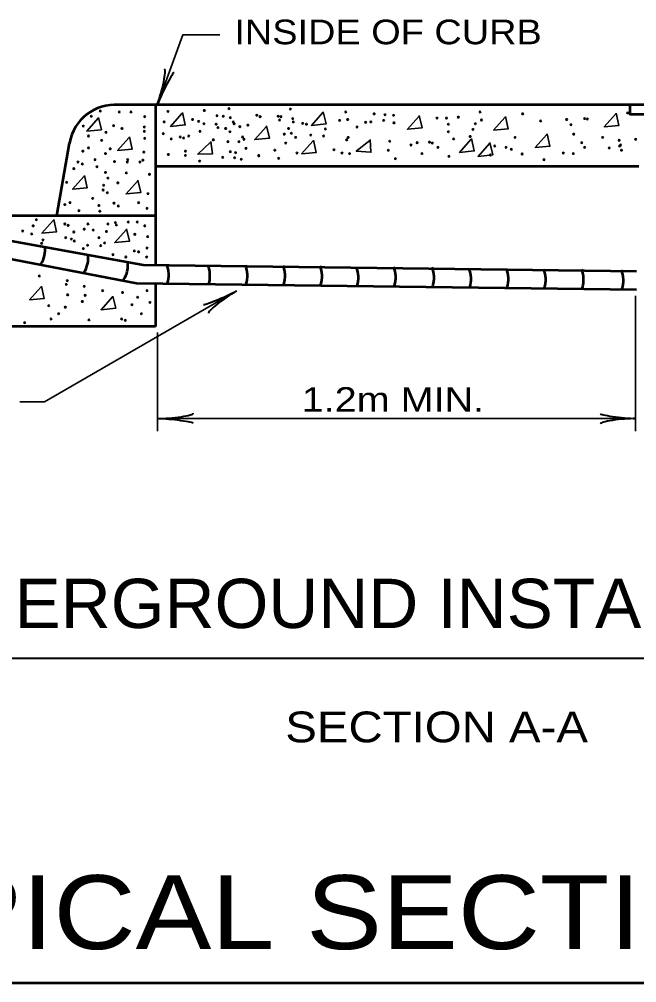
# Model space of a CAD drawing. Extents: x -90 to 623, y -379 to 75.
# Drawn here: x 22.4 to 72.5, y -115.6 to -37.4 of the extents above; entities that cross this region are included whole.
import ezdxf

# ---------------------------------------------------------------- set-up
doc = ezdxf.new("R2010")
doc.units = 0
doc.header["$LTSCALE"] = 0.8
doc.layers.add('1', color=7, linetype='Continuous', lineweight=35)

msp = doc.modelspace()

# ---------------------------------------------------------------- linework, layer by layer
at = {"layer": '1', "lineweight": 53}
for p, q in [((95.4567, -44.3181), (30.4567, -44.3181)), ((33.4567, -44.3181), (33.4567, -57.3237)), ((25.4567, -53.3181), (26.4986, -47.4093)), ((72.7067, -49.3181), (33.4567, -49.3181)), ((33.4567, -53.3181), (3.4567, -53.3181)), ((3.4567, -53.3181), (31.9376, -58.7988)), ((10.4567, -53.3181), (32.4567, -57.3053)), ((32.4567, -57.3053), (72.5202, -57.8181)), ((31.9376, -58.7988), (72.501, -59.318)), ((33.4567, -58.7824), (33.4567, -62.3181)), ((33.4567, -62.3181), (3.4567, -62.3181)), ((0.8544, -115.6087), (216.8702, -115.6087))]:
    msp.add_line(p, q, dxfattribs=at)
at = {"layer": '1'}
for p, q in [((72.4397, -59.8188), (72.4397, -70.8188)), ((33.6269, -62.8061), (33.6269, -70.8188)), ((33.6609, -69.7865), (72.4412, -69.7865))]:
    msp.add_line(p, q, dxfattribs=at)
at = {"layer": '1', "lineweight": 40}
msp.add_line((7.4085, -89.2559), (100.8059, -89.2559), dxfattribs=at)
at = {"layer": '1'}
for points in [[(33.6255, -44.2669), (35.6776, -38.6287), (38.6776, -38.6287)], [(28.8155, -45.4032), (27.8942, -46.4397), (29.0842, -46.3246), (28.8538, -45.3265)], [(35.6102, -45.0193), (34.6888, -46.0558), (35.8788, -45.9407), (35.6485, -44.9426)], [(47.0498, -44.9426), (46.1285, -45.9791), (47.3185, -45.8639), (47.0882, -44.8658)], [(54.8426, -45.2497), (53.9213, -46.2862), (55.1112, -46.171), (54.8809, -45.1729)], [(61.8292, -45.3264), (60.9079, -46.3629), (62.0979, -46.2477), (61.8676, -45.2497)], [(70.812, -45.0577), (69.8907, -46.0942), (71.0807, -45.9791), (70.8503, -44.981)], [(42.4432, -46.0942), (41.5219, -47.1307), (42.7119, -47.0156), (42.4816, -46.0175)], [(31.3107, -46.9771), (30.3893, -48.0136), (31.5793, -47.8984), (31.349, -46.9003)], [(65.2073, -46.7468), (64.286, -47.7833), (65.476, -47.6682), (65.2457, -46.6701)], [(37.9037, -47.3589), (36.8955, -48.3112), (38.091, -48.3002), (37.9485, -47.2858)], [(46.2437, -47.2458), (45.3223, -48.2823), (46.5123, -48.1672), (46.282, -47.1691)], [(50.8516, -47.1979), (49.7642, -48.0587), (50.9562, -48.1519), (50.9026, -47.129)], [(59.0652, -47.1307), (58.1439, -48.1672), (59.3339, -48.052), (59.1036, -47.0539)], [(60.5674, -47.4546), (59.6461, -48.4911), (60.8361, -48.3759), (60.6058, -47.3778)], [(27.6638, -50.1249), (26.7425, -51.1614), (27.9325, -51.0463), (27.7022, -50.0482)], [(32.0017, -50.5088), (31.0803, -51.5453), (32.2703, -51.4302), (32.04, -50.4321)], [(25.1686, -53.695), (24.2472, -54.7315), (25.4372, -54.6163), (25.2069, -53.6182)], [(31.0803, -54.4628), (30.159, -55.4993), (31.349, -55.3842), (31.1187, -54.3861)], [(40.0432, -59.4234), (24.4548, -68.4234), (22.4548, -68.4234)], [(24.1705, -59.1077), (23.2492, -60.1442), (24.4392, -60.0291), (24.2088, -59.031)], [(29.9671, -59.9139), (29.0457, -60.9504), (30.2357, -60.8352), (30.0054, -59.8372)]]:
    msp.add_lwpolyline(points, dxfattribs=at)
at = {"layer": '1', "lineweight": 53}
msp.add_lwpolyline([(71.9567, -44.3181), (71.9567, -45.0681), (86.4567, -45.0681), (86.4567, -44.3181)], dxfattribs=at)
at = {"layer": '1'}
for centre in [(39.4299, -44.6158), (44.4204, -44.6542), (28.2589, -45.2301), (28.9883, -44.8078), (30.5238, -44.8846), (31.4836, -44.8846), (32.5968, -45.2685), (34.4778, -44.8462), (37.4337, -44.7694), (38.4703, -45.1917), (38.9692, -45.2301), (39.5451, -45.3453), (41.6948, -45.1533), (41.9636, -45.2685), (43.4223, -45.2301), (43.6527, -45.2685), (44.6123, -45.422), (48.9118, -44.8846), (51.2151, -45.0382), (52.098, -45.1149), (52.789, -45.1533), (56.3207, -45.3837), (57.0885, -45.3837), (58.0482, -45.3068), (59.814, -44.8846), (63.2689, -45.0382), (68.2977, -45.422), (71.7911, -44.9613), (27.6063, -46.0362), (30.0632, -45.9978), (30.7542, -46.2282), (32.5584, -46.113), (34.1707, -45.6908), (36.474, -45.4988), (36.9731, -45.6523), (37.3954, -45.8442), (38.3935, -45.8827), (38.547, -46.1514), (39.1612, -46.2282), (39.7754, -45.6908), (39.8522, -45.8442), (40.3128, -46.0746), (40.9655, -45.9594), (43.5375, -45.5372), (44.2668, -46.2282), (44.6507, -45.6908), (45.4185, -45.8059), (45.7256, -45.8827), (48.4127, -45.5756), (49.0653, -45.4988), (49.8331, -46.113), (50.5241, -45.7291), (50.9463, -45.6908), (51.9828, -45.5756), (52.8274, -45.7675), (57.242, -45.8827), (59.4302, -45.8442), (59.9292, -45.5372), (64.7277, -45.614), (66.839, -45.4988), (67.1845, -45.9211), (68.5281, -45.4604), (28.0287, -46.8424), (29.449, -46.5353), (32.5584, -46.4585), (34.0939, -46.6505), (35.4759, -46.9192), (35.7447, -46.9959), (36.1669, -46.8424), (37.0883, -46.4585), (39.5067, -46.4969), (40.5432, -46.9192), (43.9213, -46.6888), (44.4972, -46.6121), (44.8427, -46.9576), (46.0711, -46.7656), (47.1076, -46.8424), (47.2611, -46.2666), (49.1037, -46.9576), (57.242, -46.4969), (59.0078, -46.8807), (59.2382, -46.3049), (62.6547, -46.9576), (67.4148, -46.6888), (69.7565, -46.9576), (29.1035, -47.1879), (32.5968, -47.0343), (34.7465, -47.0727), (38.1632, -47.1495), (39.3532, -47.303), (40.2361, -47.303), (40.6583, -47.1111), (44.0365, -47.4182), (48.9886, -47.1495), (52.4819, -47.2647), (54.2093, -47.5718), (54.7084, -47.3798), (55.7065, -47.3414), (55.9368, -47.4182), (56.3975, -47.7637), (57.6642, -47.0727), (61.0041, -47.6485), (61.9253, -47.7637), (68.0675, -47.3798), (68.2977, -47.7637), (71.1001, -47.1878), (71.1385, -47.6485), (71.2152, -47.5718), (72.4437, -47.1111), (27.568, -48.0708), (28.0287, -47.8021), (29.4106, -48.2627), (29.7945, -47.8789), (32.52, -48.1476), (34.5162, -48.3395), (35.8982, -48.0708), (35.8982, -48.4163), (38.9309, -48.5698), (39.5451, -48.1092), (39.9674, -48.186), (40.8119, -47.8405), (41.8484, -48.4162), (41.8484, -48.4547), (43.1536, -47.994), (44.9578, -48.2243), (47.9521, -47.9557), (48.6047, -48.2243), (49.2189, -48.2627), (52.3667, -47.994), (55.0922, -48.2627), (57.2804, -48.4931), (60.6586, -48.3779), (62.3477, -47.9172), (63.2306, -48.3011), (66.5703, -48.2243), (67.3765, -48.2627), (70.294, -47.8021), (71.2921, -47.994), (27.1841, -48.9537), (27.5296, -49.1073), (28.5661, -48.7618), (28.7196, -49.3377), (30.14, -48.9153), (31.1764, -48.9537), (31.2148, -48.7618), (32.2129, -48.9537), (32.4432, -48.8002), (37.0498, -48.877), (39.8906, -48.6082), (40.428, -48.7234), (43.4607, -48.6466), (52.9426, -48.685), (64.9964, -48.7617), (26.8386, -49.4912), (29.4106, -49.7982), (31.0997, -49.8367), (32.9807, -49.9518), (26.2628, -50.6044), (29.2571, -50.8347), (29.6025, -50.2589), (30.4087, -50.6428), (29.2187, -51.2187), (29.5642, -51.449), (32.8655, -51.5257), (26.1092, -52.4087), (26.5315, -52.2551), (28.3741, -51.9097), (28.8732, -52.4854), (30.1016, -52.2935), (32.0977, -52.2551), (27.2608, -52.9078), (28.9499, -52.9461), (30.4471, -52.5238), (32.7888, -52.7157), (23.8059, -53.6371), (26.1092, -53.9826), (27.9902, -53.9826), (29.6025, -53.9826), (30.2167, -53.8674), (31.2532, -53.829), (31.9826, -53.829), (22.6927, -54.5584), (23.4221, -54.7888), (23.5373, -54.1362), (26.3779, -54.0977), (26.8386, -54.6352), (27.6832, -54.4048), (28.4125, -54.4817), (29.4873, -54.5968), (30.2935, -54.0593), (31.7907, -54.8272), (32.5968, -54.1362), (24.2282, -55.5565), (24.3433, -55.2877), (26.186, -55.0958), (26.6467, -55.211), (26.877, -55.3646), (28.8732, -55.0958), (29.3338, -55.5181), (32.8272, -55.0191), (27.6063, -55.9787), (27.9518, -55.7101), (29.0267, -55.7484), (31.7523, -56.1707), (32.0977, -56.2475), (32.7888, -55.9404), (30.0248, -56.4778), (31.0612, -56.6698), (32.7503, -56.6698), (24.0362, -58.2053), (26.3012, -58.5892), (26.2244, -58.8963), (27.6832, -59.0498), (29.1802, -59.3953), (32.7888, -59.3953), (26.3396, -59.7408), (27.5296, -60.2782), (27.7599, -59.7792), (30.7926, -59.5489), (32.021, -59.9328), (24.8041, -60.6238), (26.1477, -60.7389), (31.5603, -60.547), (33.0191, -60.3551), (24.996, -61.6987), (25.6102, -61.2764), (28.067, -61.7754), (30.7158, -61.6987), (31.0229, -61.8138), (32.3281, -61.2764), (22.8462, -62.0057)]:
    msp.add_circle(centre, 0.0607, dxfattribs=at)
at = {"layer": '1', "lineweight": 53}
for centre, radius, start, end in [((30.1685, -48.0287), 3.7218, 85.55938, 170.41856), ((22.3448, -56.0724), 2.1707, 327.00343, 7.84739), ((25.8381, -56.7634), 2.1707, 327.00343, 7.84739), ((29.0627, -57.3393), 2.1707, 327.00343, 7.84739), ((32.382, -58.1124), 2.1707, 342.00343, 22.84739), ((35.7218, -58.1892), 2.1707, 342.00343, 22.84739), ((38.7544, -58.1892), 2.1707, 342.00343, 22.84739), ((41.8254, -58.1892), 2.1707, 342.00343, 22.84739), ((44.8197, -58.2276), 2.1707, 342.00343, 22.84739), ((47.7756, -58.3428), 2.1707, 342.00343, 22.84739), ((50.8083, -58.3044), 2.1707, 342.00343, 22.84739), ((53.9177, -58.3428), 2.1707, 342.00343, 22.84739), ((56.9119, -58.458), 2.1707, 342.00343, 22.84739), ((59.9446, -58.458), 2.1707, 342.00343, 22.84739), ((62.9773, -58.4964), 2.1707, 342.00343, 22.84739), ((66.0484, -58.5347), 2.1707, 342.00343, 22.84739), ((69.2729, -58.5731), 2.1707, 342.00343, 22.84739)]:
    msp.add_arc(centre, radius, start, end, dxfattribs=at)
at = {"layer": '1', "lineweight": 40}
for centre, major_axis, ratio, start_param, end_param in [((33.7391, -43.147), (-0.464, -1.7314), 0.122415, 0.8963533, 3.1415927), ((34.2076, -43.2864), (0.7658, 1.5905), 0.07063, 6.2823074, 8.5597026), ((38.967, -59.8004), (1.609, 0.7261), 0.07063, 3.1407148, 5.41811), ((38.967, -59.8004), (1.609, 0.7261), 0.07063, 3.1407148, 5.41811), ((39.2363, -60.2083), (1.4684, 1.0281), 0.122415, 0.8963533, 3.1415927), ((39.2363, -60.2083), (1.4684, 1.0281), 0.122415, 0.8963533, 3.1415927), ((34.7521, -69.5102), (-1.7857, -0.1562), 0.122415, 0.8963533, 3.1415927), ((71.3207, -69.5749), (1.7565, -0.1757), 0.07063, 3.1407148, 5.41811), ((34.7814, -69.9981), (1.7565, -0.1757), 0.07063, 6.2823074, 8.5597026), ((71.35, -70.0628), (1.7857, 0.1562), 0.122415, 0.8963533, 3.1415927)]:
    msp.add_ellipse(centre, major_axis=major_axis, ratio=ratio, start_param=start_param, end_param=end_param, dxfattribs=at)

# ---------------------------------------------------------------- texts
at = {"layer": '1'}
for s, height, width, p in [('INSIDE OF CURB', 2, 1.15, (39.869, -39.3877)), ('1.2m MIN.', 2, 1.2, (45.3354, -69.2403)), ('UNDERGROUND INSTALLATION', 4, 1.05, (9.8662, -86.7986)), ('SECTION A-A', 2.5, 1.15, (44.0028, -96.0832)), ('TYPICAL SECTION IN GUTTER AND SIDEWALK', 6, 1.15, (4.6777, -112.8777))]:
    msp.add_text(s, height=height, dxfattribs=dict(at, width=width)).set_placement(p)

doc.saveas('drawing.dxf')
